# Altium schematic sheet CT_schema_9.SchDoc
size 278 x 170 mm
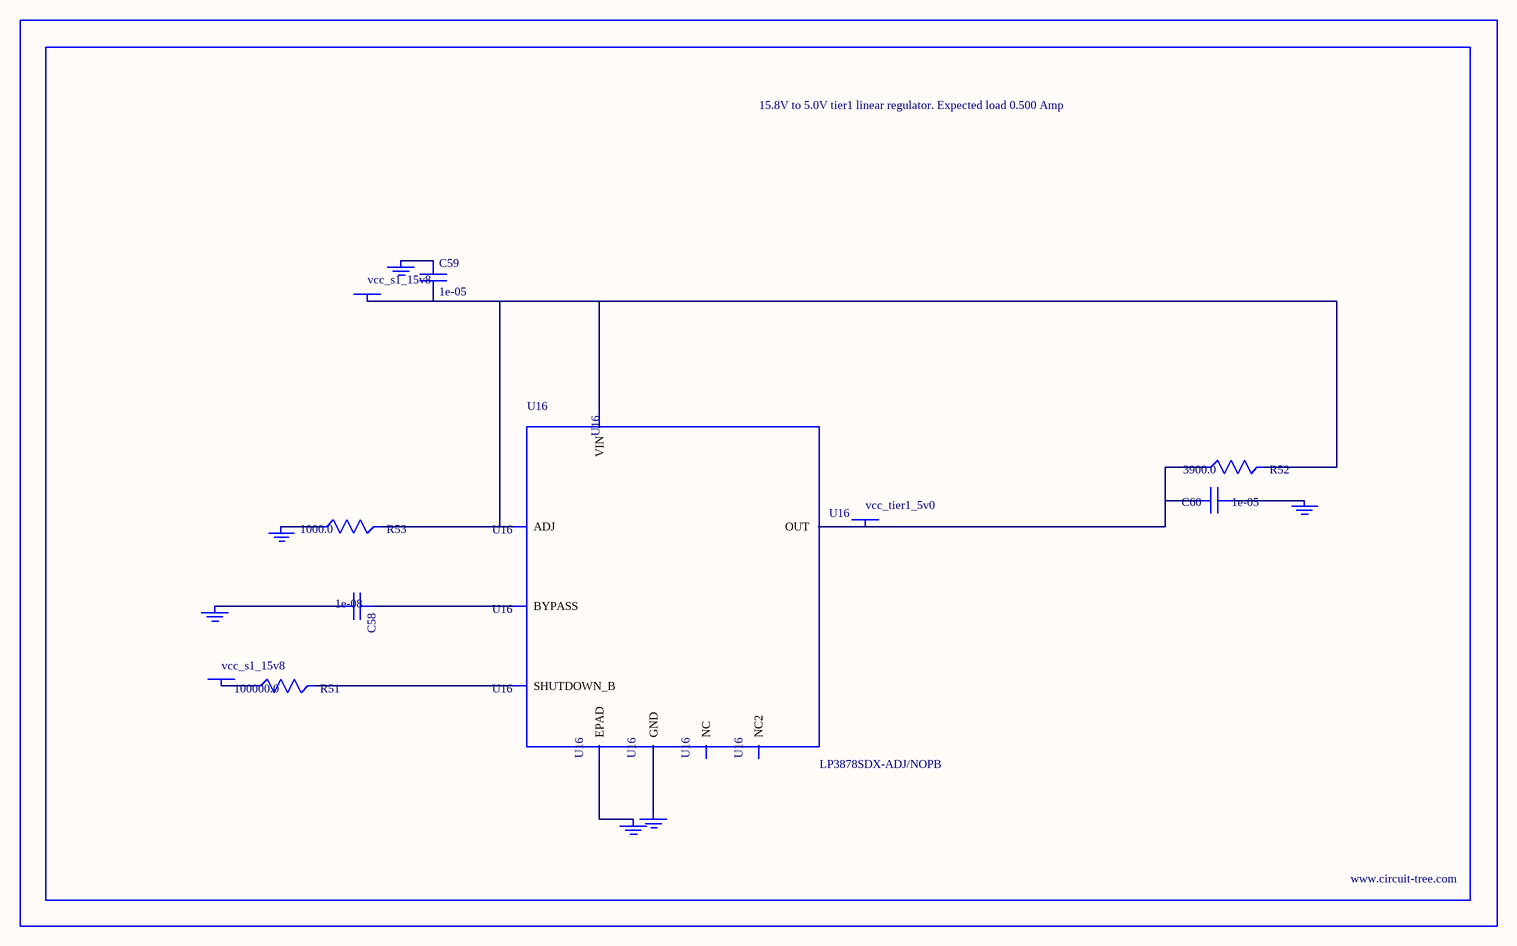
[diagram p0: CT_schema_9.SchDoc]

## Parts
BORDER8  (no value)
C58  1e-08  [C0402]
C59  1e-05  [C1210]
C60  1e-05  [C1210]
GND_INSTANCE_8_0  (no value)
GND_INSTANCE_8_1  (no value)
GND_INSTANCE_8_2  (no value)
GND_INSTANCE_8_3  (no value)
GND_INSTANCE_8_4  (no value)
GND_INSTANCE_8_5  (no value)
POWER_INSTANCE_8_0  vcc_s1_15v8
POWER_INSTANCE_8_1  vcc_s1_15v8
POWER_INSTANCE_8_2  vcc_tier1_5v0
R51  100000.0  [R0603]
R52  3900.0  [R0603]
R53  1000.0  [R0603]
U16  LP3878SDX-ADJ/NOPB  [WSON-8]

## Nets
NetC58_1: C58.1 U16.1(BYPASS)
NetC58_2: C58.2 GND_INSTANCE_8_0.0(GND)
NetC59_1: C59.1 GND_INSTANCE_8_1.0(GND)
NetC59_2: C59.2 POWER_INSTANCE_8_0.0(PWR) R52.2 R53.2 U16.4(VIN) U16.6(ADJ)
NetC60_1: C60.1 GND_INSTANCE_8_2.0(GND)
NetC60_2: C60.2 POWER_INSTANCE_8_2.0(PWR) R52.1 U16.5(OUT)
NetGND_INSTANCE_8_3_0: GND_INSTANCE_8_3.0(GND) R53.1
NetGND_INSTANCE_8_4_0: GND_INSTANCE_8_4.0(GND) U16.PAD(EPAD)
NetGND_INSTANCE_8_5_0: GND_INSTANCE_8_5.0(GND) U16.3(GND)
NetPOWER_INSTANCE_8_1_0: POWER_INSTANCE_8_1.0(PWR) R51.1
NetR51_2: R51.2 U16.8(SHUTDOWN_B)

Not connected (* = marked no-connect by the designer): U16 2(NC) 7(NC2)

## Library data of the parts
BORDER8 = BORDER_PAGE8
C58 = C0402C103K3RAC
C59 = C1210C106K5PACTU
C60 = GRM32DR61E106MA12L
GND_INSTANCE_8_0-GND_INSTANCE_8_5 = GND
POWER_INSTANCE_8_0-POWER_INSTANCE_8_2 = PWR
R51 = RC0603JR-07100KL
R52 = RC0603JR-073K9L
R53 = RC0603JR-071KL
